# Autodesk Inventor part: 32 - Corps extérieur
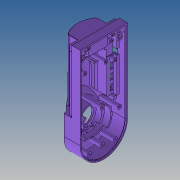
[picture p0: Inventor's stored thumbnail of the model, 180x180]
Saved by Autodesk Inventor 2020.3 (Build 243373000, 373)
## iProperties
Created: 2021-09
Part Number: 32 - Corps extérieur
Material: Aluminium 6061
Document SubType Name: Modeling
Designer: JP
Density: 2.7 g/cm^3
Appearance: Violet
Author: JP
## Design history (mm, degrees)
sketch "Esquisse1"
  geometry: L1 (-33.25, 0)-(-33.25, -115.85); L2 (-33.25, -115.85)-(33.25, -115.85); L3 (33.25, -115.85)-(33.25, 0); A1 r 33.25 centre (0, 0) between (33.25, 0) and (-33.25, 0); 1 further point
  constraints: 6 end point, 2 perpendicular, 2 point on circle, 2 tangent, 1 centre point, 1 coincident, 1 horizontal
  dimensions: "d0" = 115.85 distance of L1.start L1.end; "d1" = 33.25 radius of A1
extrude "Extrusion1" new body sketch "Esquisse1" distance "d2" = 38.6; taper "d3" = 0 deg
sketch "Esquisse2"
  geometry: L1 (0, 0)-(66.5, 0) reference; L2 (66.5, 0)-(66.5, 38.6) reference; L3 (0, 38.6)-(66.5, 38.6) reference; L4 (0, 0)-(0, 38.6) reference; L5 (33.25, -7.72)-(33.25, 46.32) reference; A1 r 33.95 centre (33.25, 4.65) between (59.533, 26.14) and (6.967, 26.14); A2 r 9 centre (66.5, 31.837) between (59.533, 26.14) and (65.6, 22.882); A3 r 1 centre (65.5, 21.887) between (66.5, 21.887) and (65.6, 22.882); A4 r 9 centre (0, 31.837) between (0.9, 22.882) and (6.967, 26.14); A5 r 1 centre (1, 21.887) between (0.9, 22.882) and (0, 21.887); 2 further points
  constraints: 10 point on circle, 5 centre point, 4 point on line, 3 tangent, 2 other
  dimensions: "d4" = 33.95 radius of A1; "d5" = 4.65 distance from line of L1 A1.centre; "d6" = 9 radius of A2; "d7" = 1 radius of A3
extrude "Extrusion2" cut sketch "Esquisse2" extent not by distance; stored distance "d8" = 0; taper "d9" = 0 deg
sketch "Esquisse3"
  geometry: L1 (0, 149.1)-(38.6, 149.1) reference; L2 (38.6, 149.1)-(38.6, 0) reference; L3 (0, 115.85)-(0, 149.1) reference; A1 r 169.8 centre (193.3, 149.1) between (23.5, 149.1) and (38.6, 79.1)
  constraints: 2 point on circle, 2 point on line, 1 centre point
  dimensions: "d10" = 339.6 diameter of A1; "d11" = 23.5 distance from line of L3 A1.start; "d12" = 70 distance from line of L1 A1.end
extrude "Extrusion3" cut sketch "Esquisse3" extent not by distance; stored distance "d13" = 0.002; taper "d14" = 0 deg
sketch "Esquisse4"
  geometry: L1 (0, 0)-(0, 21.887) reference; L2 (0, 0)-(66.5, 0) reference; L3 (66.5, 0)-(66.5, 21.887) reference; L4 (0, 11.5)-(3.5, 11.5); L5 (3.5, 11.5)-(3.5, 13.3); L6 (3.5, 13.3)-(2.075, 13.3); L7 (2.075, 13.3)-(2.075, 16.3); L8 (2.075, 16.3)-(12.75, 16.3); L9 (12.75, 27.305)-(12.75, 16.3); L10 (33.096, 23.5)-(33.404, 23.5) reference; L11 (66.5, 11.5)-(63, 11.5); L12 (63, 11.5)-(63, 13.3); L13 (63, 13.3)-(64.425, 13.3); L14 (64.425, 13.3)-(64.425, 16.3); L15 (64.425, 16.3)-(53.75, 16.3); L16 (53.75, 16.3)-(53.75, 27.305); L17 (33.25, -7.721)-(33.25, 46.324) reference; A1 r 1 centre (65.5, 21.887) between (66.5, 21.887) and (65.6, 22.882) reference; A2 r 33.95 centre (33.25, 4.65) between (59.533, 26.14) and (6.967, 26.14) reference; A3 r 1 centre (1, 21.887) between (0.9, 22.882) and (0, 21.887) reference; A4 r 32.45 centre (33.25, 4.65) between (51.573, 31.432) and (14.927, 31.432); A5 r 5 centre (17.75, 27.305) between (14.927, 31.432) and (12.75, 27.305); A6 r 5 centre (48.75, 27.305) between (53.75, 27.305) and (51.573, 31.432); A7 r 9 centre (0, 31.837) between (0.9, 22.882) and (6.967, 26.14) reference; A8 r 9 centre (66.5, 31.837) between (59.533, 26.14) and (65.6, 22.882) reference; 2 further points
  constraints: 24 end point, 10 perpendicular, 7 point on circle, 4 tangent, 3 centre point, 3 point on line, 1 equal radius, 1 horizontal, 1 parallel, 6 other
  dimensions: "d15" = 3.5 distance of L4.start L4.end; "d16" = 11.5 distance between parallel lines of L2 L11; "d17" = 1.8 distance of L4.end L5.end; "d18" = 62.35 distance between parallel lines of L14 L7; "d19" = 3 distance of L6.end L7.end; "d20" = 1.5 radial gap between concentric circles of A2 A4; "d21" = 5 radius of A5; "d23" = 41 distance between parallel lines of L16 L9
extrude "Extrusion4" cut sketch "Esquisse4" distance "d24" = 88; taper "d25" = 0 deg
sketch "Esquisse5"
  geometry: L1 (45.062, 34.874)-(48.714, 34.874) reference; L2 (49.25, 34.593)-(49.25, 32.881); L3 (33.25, -7.782)-(33.25, 46.69) reference; L4 (17.25, 34.593)-(17.25, 32.881); A1 r 32.45 centre (33.25, 4.65) between (51.573, 31.432) and (45.062, 34.874) reference; A2 r 5 centre (48.75, 27.305) between (53.75, 27.305) and (51.573, 31.432) reference; A3 r 33.95 centre (33.25, 4.65) between (59.533, 26.14) and (48.714, 34.874) reference; A4 r 33.95 centre (33.25, 4.65) between (49.25, 34.593) and (16.125, 33.964); A5 r 32.45 centre (33.25, 4.65) between (51.573, 31.432) and (16.125, 32.213); A6 r 32.45 centre (33.25, 4.65) between (21.438, 34.874) and (14.927, 31.432) reference; 11 further points
  constraints: 8 point on circle, 4 end point, 3 concentric, 2 centre point, 2 vertical, 1 coincident, 3 other
  dimensions: "d30" = 32 distance between parallel lines of L2 L4
extrude "Extrusion5" join sketch "Esquisse5" distance "d26" = 46; taper "d28" = 0 deg; dims "d27" = 28, "d29" = 0
node "Plan de construction1"
sketch "Esquisse6"
  geometry: C1 r 169.8 at (-193.3, 149.1); A1 r 169.8 centre (-193.3, 149.1) between (-34.593, 88.732) and (-32.881, 93.441) reference; 3 further points
  constraints: 2 concentric, 1 centre point, 1 other
extrude "Extrusion6" cut sketch "Esquisse6" extent not by distance; stored distance "d31" = 0.002; taper "d32" = 0 deg
sketch "Esquisse7"
  geometry: L1 (-16, 42)-(16, 42) reference; L2 (-16, 42)-(-16, 58); L3 (16, 88)-(16, 42) reference; L4 (16, 42)-(16, 58); A1 r 16 centre (0, 58) between (-16, 58) and (0, 42); A2 r 16 centre (0, 58) between (0, 42) and (16, 58); 1 further point
  constraints: 4 end point, 4 point on circle, 2 centre point, 1 concentric, 1 midpoint, 1 parallel, 1 point on line, 1 tangent, 1 vertical
  dimensions: "d33" = 16 radius of A1
extrude "Extrusion7" cut sketch "Esquisse7" stored distance "d34" = 10; taper "d35" = 0 deg; dims "d11" = 23.5
chamfer "Chanfrein1" distance "d36" = 5; stored, may be unused: second distance "d37" = 2, angle "d38" = 45 deg
node "Plan de construction2"
sketch "Esquisse8"
  geometry: L1 (0, -145.67)-(0, 63.072) reference; L2 (12, -95.15)-(-12, -95.15); L3 (-12, -95.15)-(-12, -111.15); L4 (-12, -111.15)-(12, -111.15); L5 (12, -111.15)-(12, -95.15); L6 (33.25, -115.85)-(-33.25, -115.85) reference; 1 further point
  constraints: 8 end point, 2 parallel, 1 horizontal, 1 perpendicular, 1 other
  dimensions: "d40" = 24 distance of L4.end L3.end; "d41" = 16 distance of L3.end L2.end; "d42" = 4.7 distance between parallel lines of L6 L4
extrude "Extrusion8" cut sketch "Esquisse8" extent not by distance; stored distance "d43" = 10; taper "d44" = 3.5 deg
sketch "Esquisse9"
  geometry: L1 (-112.628, 34.168)-(-93.672, 34.168) reference; L2 (-111.15, 10)-(-112.628, 34.168) reference; L3 (-111.15, 10)-(-95.15, 10) reference; L4 (-95.15, 10)-(-93.672, 34.168) reference; L5 (-111.15, 10)-(-95.15, 10) reference; L6 (-95.15, 10)-(-79.504, 37.1); L7 (-115.85, 27.305)-(-115.85, 16.3) reference; L8 (-73.85, 37.1)-(-115.85, 37.1) reference; L9 (-95.15, 10)-(-111.15, 10); L10 (-115.85, 11.5)-(-27.85, 11.5) reference; L11 (-111.15, 10)-(-112.628, 34.168) reference; L12 (-112.808, 37.1)-(-111.15, 10); A1 r 21.987 centre (-89.204, 11.342) between (-111.15, 10) and (-111.15, 10); 4 further points
  constraints: 6 end point, 3 point on line, 2 point on circle, 1 centre point, 1 collinear, 1 parallel, 1 tangent
  dimensions: "d45" = 30 deg angle of L7 L6
extrude "Extrusion9" cut sketch "Esquisse9" stored distance "d46" = 10; taper "d47" = 0 deg
mirror "Symétrie1"
sketch "Esquisse10"
  geometry: L1 (3.5, 0)-(0, 0) reference; L2 (3.5, 88)-(3.5, 0) reference; L3 (3.5, 0)-(-63, 0); L4 (-63, 0)-(-63, 2); L5 (-63, 2)-(3.5, 2); L6 (3.5, 2)-(3.5, 0); L7 (-63, 0)-(-63, 88) reference; 3 further points
  constraints: 8 end point, 2 parallel, 1 collinear, 1 horizontal, 1 perpendicular
  dimensions: "d48" = 2 distance of L3.end L4.end
extrude "Extrusion10" cut sketch "Esquisse10" extent not by distance; stored distance "d49" = 27.105; taper "d50" = 0 deg
fillet "Congé1" dims "d51" = 0.5
feature "Coque1" dims "d52" = 2
sketch "Esquisse12"
  geometry: L1 (0, 0)-(22.906, 0) reference; L2 (11.453, 40.335)-(11.453, -117.021) reference; L3 (20.453, -25)-(2.453, -25); L4 (2.453, -25)-(2.453, -2.5); L5 (2.453, -2.5)-(20.453, -2.5); L6 (20.453, -2.5)-(20.453, -25); 1 further point
  constraints: 8 end point, 2 parallel, 1 horizontal, 1 perpendicular, 1 other
  dimensions: "d58" = 18 distance of L4.end L5.end; "d59" = 2.5 distance between parallel lines of L1 L5; "d60" = 22.5 distance of L3.end L4.end
extrude "Extrusion12" cut sketch "Esquisse12" stored distance "d61" = 10; taper "d62" = 0 deg
sketch "Esquisse13"
  geometry: L1 (-1, -86)-(10.175, -86) reference; L2 (10.175, -86)-(10.175, 0) reference; L3 (-52.175, -86)-(-41, -86) reference; L4 (-41.5, -85.5)-(-41.5, -0.5) reference; L5 (-41.5, -0.5)-(-42, 0) reference; L6 (-42, 0)-(-52.175, 0) reference; L7 (-52.175, -86)-(-52.175, 0) reference; L8 (-52.25, -78)-(-44.95, -78); L9 (-41.95, -81)-(-41.95, -86); L10 (-41.95, -86)-(-52.25, -86); L11 (-52.25, -86)-(-52.25, -78); L12 (10.25, -78)-(2.95, -78); L13 (-0.05, -81)-(-0.05, -86); L14 (-0.05, -86)-(10.25, -86); L15 (10.25, -86)-(10.25, -78); L16 (12.25, -88)-(-54.25, -88) reference; L17 (-21, -117.82)-(-21, 90.922) reference; L18 (10.25, -86)-(10.25, 27.85) reference; L19 (-52.25, 27.85)-(-52.25, -86) reference; A1 r 0.5 centre (-41, -85.5) between (-41.5, -85.5) and (-41, -86) reference; A2 r 3 centre (-44.95, -81) between (-41.95, -81) and (-44.95, -78); A3 r 3 centre (2.95, -81) between (2.95, -78) and (-0.05, -81); 7 further points
  constraints: 16 end point, 4 parallel, 4 point on circle, 4 tangent, 2 centre point, 2 collinear, 2 horizontal, 2 perpendicular, 1 equal radius, 1 point on line, 1 symmetric about line, 1 other
  dimensions: "d63" = 3 radius of A2; "d64" = 10 distance between parallel lines of L16 L8; "d65" = 47.9 distance of A3.centre A2.centre
extrude "Extrusion13" join sketch "Esquisse13" stored distance "d66" = 10; taper "d67" = 0 deg
sketch "Esquisse14"
  geometry: L1 (-52.25, -86)-(-41, -86) reference; L2 (-41.5, -85.5)-(-41.5, -0.5) reference; L3 (-41.5, -0.5)-(-42, 0) reference; L4 (-42, 0)-(-52.175, 0) reference; L5 (-52.175, -78)-(-52.175, 0) reference; L6 (-52.175, -78)-(-52.25, -78) reference; L7 (-52.25, -78)-(-52.25, -86) reference; L8 (-21, -117.82)-(-21, 90.922) reference; L9 (12.25, -88)-(-54.25, -88) reference; C1 r 4.1 at (-47.4, -71.8); C2 r 4.1 at (5.4, -71.8); A1 r 0.5 centre (-41, -85.5) between (-41.5, -85.5) and (-41, -86) reference; 1 further point
  constraints: 2 centre point, 1 other
  dimensions: "d68" = 8.2 diameter of C1; "d69" = 16.2 distance from line of L9 C1.centre; "d70" = 52.8 distance of C2.centre C1.centre
extrude "Extrusion14" join sketch "Esquisse14" distance "d71" = 2; taper "d73" = 0 deg; dims "d72" = 12.2, "d74" = 0
sketch "Esquisse15"
  geometry: L1 (-26.4, -46.02)-(-26.4, 162.722) reference; L2 (6.85, -16.2)-(-59.65, -16.2) reference; C1 r 2.5 at (-9.65, -7.9); C2 r 2.5 at (-43.15, -7.9); 1 further point
  constraints: 2 centre point, 1 other
  dimensions: "d75" = 5 diameter of C1; "d76" = 8.3 distance from line of L2 C2.centre; "d77" = 33.5 distance of C1.centre C2.centre
extrude "Extrusion15" join sketch "Esquisse15" stored distance "d78" = 10; taper "d79" = 0 deg
node "Plan de construction3"
sketch "Esquisse16"
  geometry: L1 (27.75, -119.82)-(27.75, 88.922) reference; L2 (61, -90)-(-5.5, -90) reference; C1 r 2.5 at (13.25, -46.3); C2 r 2.5 at (5.75, -68.1); C3 r 2.5 at (42.25, -46.3); C4 r 2.5 at (49.75, -68.1); 1 further point
  constraints: 4 centre point, 1 equal radius, 2 other
  dimensions: "d81" = 5 diameter of C1; "d82" = 43.7 distance from line of C1.centre L2; "d83" = 21.9 distance from line of L2 C2.centre; "d84" = 29 distance of C3.centre C1.centre; "d85" = 44 distance of C4.centre C2.centre
extrude "Extrusion16" join sketch "Esquisse16" stored distance "d86" = 10; taper "d87" = 0 deg
node "Plan de construction4"
sketch "Esquisse17"
  geometry: L1 (27.75, -119.82)-(27.75, 88.922) reference; L2 (61, -90)-(-5.5, -90) reference; C1 r 2.5 at (2.75, 1.2); C2 r 2.5 at (52.75, 1.2); C3 r 2.5 at (2.75, -44.7); C4 r 2.5 at (52.75, -44.7); 1 further point
  constraints: 4 centre point, 1 equal radius, 1 vertical alignment, 2 other
  dimensions: "d89" = 5 diameter of C1; "d90" = 45.3 distance from line of L2 C3.centre; "d91" = 50 distance of C4.centre C3.centre; "d92" = 45.9 distance of C1.centre C3.centre
extrude "Extrusion17" join sketch "Esquisse17" stored distance "d93" = 10; taper "d94" = 0 deg
sketch "Esquisse18"
  geometry: L1 (0, -145.67)-(0, 63.072) reference; L2 (33.25, -115.85)-(-33.25, -115.85) reference; C1 r 3 at (-18.2, 18.949); C2 r 3 at (18.2, 18.949); C3 r 3 at (23.95, -17.5); C4 r 3 at (-23.95, -17.5); C5 r 3 at (0, -28.95); C6 r 3 at (0, 16.65); A1 r 3 centre (-23.95, -108.85) between (-20.95, -108.85) and (-23.95, -105.85) reference; A2 r 31.25 centre (0, 0) between (31.25, 0) and (-31.25, 0) reference; A3 r 3 centre (23.95, -108.85) between (23.95, -105.85) and (20.95, -108.85) reference
  constraints: 6 centre point, 3 equal radius, 2 point on line, 2 other
  dimensions: "d95" = 6 diameter of C1; "d96" = 36.4 distance of C2.centre C1.centre; "d97" = 91.35 distance of A1.centre C4.centre; "d98" = 47.9 distance of C3.centre C4.centre; "d99" = 36.9 distance of C4.centre C1.centre; "d100" = 45.6 distance of C6.centre C5.centre; "d101" = 11.45 vertical distance of C3.centre C5.centre; "d229" = 7 distance from line of L2 A1.centre (derived); "d230" = 17.5 vertical distance of C3.centre A2.centre (derived); "d231" = 108.85 vertical distance of A3.centre A2.centre (derived)
extrude "Extrusion18" join sketch "Esquisse18" stored distance "d102" = 10; taper "d103" = 0 deg
sketch "Esquisse19"
  geometry: L1 (-23.95, -39.82)-(-23.95, 168.922) reference; L2 (-0.9, 75.2)-(3.1, 75.2); L3 (3.1, 75.2)-(3.1, 67.2); L4 (3.1, 67.2)-(-0.9, 67.2); L5 (-0.9, 67.2)-(-0.9, 75.2); L6 (-0.9, 62.2)-(3.1, 62.2); L7 (3.1, 62.2)-(3.1, 54.2); L8 (3.1, 54.2)-(-0.9, 54.2); L9 (-0.9, 54.2)-(-0.9, 62.2); L10 (-0.9, 49.2)-(3.1, 49.2); L11 (3.1, 49.2)-(3.1, 41.2); L12 (3.1, 41.2)-(-0.9, 41.2); L13 (-0.9, 41.2)-(-0.9, 49.2); L14 (-51, 75.2)-(-47, 75.2); L15 (-47, 75.2)-(-47, 67.2); L16 (-47, 67.2)-(-51, 67.2); L17 (-51, 67.2)-(-51, 75.2); L18 (-51, 62.2)-(-47, 62.2); L19 (-47, 62.2)-(-47, 54.2); L20 (-47, 54.2)-(-51, 54.2); L21 (-51, 54.2)-(-51, 62.2); L22 (-51, 49.2)-(-47, 49.2); L23 (-47, 49.2)-(-47, 41.2); L24 (-47, 41.2)-(-51, 41.2); L25 (-51, 41.2)-(-51, 49.2); L26 (9.3, 105.85)-(9.3, -10) reference; C1 r 2.5 at (1.05, 35.3) reference; C2 r 2.5 at (1.05, 35.3) reference; 1 further point
  constraints: 48 end point, 12 parallel, 6 horizontal, 6 perpendicular, 5 collinear, 5 point on line, 4 equal length, 4 other
  dimensions: "d104" = 4 distance of L3.end L4.end; "d105" = 8 distance of L2.end L3.end; "d106" = 5 distance between parallel lines of L6 L4; "d107" = 5 distance between parallel lines of L10 L8 (= d106); "d108" = 5.9 distance from line of C1.centre L12; "d109" = 6.2 distance between parallel lines of L26 L7
extrude "Extrusion19" cut sketch "Esquisse19" extent not by distance; stored distance "d110" = 14.3; taper "d111" = 0 deg
sketch "Esquisse20"
  geometry: L1 (10.175, -78)-(10.175, 0) reference; L2 (5.85, -46.1)-(10.25, -46.1); L3 (10.25, -46.1)-(10.25, -54.4); L4 (10.25, -54.4)-(5.85, -54.4); L5 (5.85, -54.4)-(5.85, -46.1); L6 (12.25, -88)-(-54.25, -88) reference; L7 (12.25, 0)-(12.25, -88) reference; L8 (10.25, -78)-(10.25, 27.85) reference; 3 further points
  constraints: 8 end point, 2 parallel, 1 collinear, 1 horizontal, 1 perpendicular
  dimensions: "d112" = 4.4 distance of L3.end L4.end; "d113" = 8.3 distance of L2.end L3.end; "d114" = 33.6 distance between parallel lines of L6 L4
extrude "Extrusion20" cut sketch "Esquisse20" extent not by distance; stored distance "d116" = 22.305; taper "d117" = 0 deg
sketch "Esquisse21"
  geometry: L1 (0, 10.071)-(0, 23.6) reference; L2 (9.25, 0.085)-(9.25, 78.328) reference; L3 (0, 31.9)-(0.9, 31.9) reference; L4 (0, 16.6)-(9.25, 16.6); L5 (9.25, 16.6)-(9.25, 31.9); L6 (9.25, 31.9)-(0, 31.9); L7 (0, 31.9)-(0, 16.6); L8 (0, 10.071)-(0, 23.6) reference; 7 further points
  constraints: 8 end point, 3 collinear, 2 parallel, 1 horizontal, 1 perpendicular
  dimensions: "d118" = 15.3 distance of L5.end L4.end
extrude "Extrusion21" cut sketch "Esquisse21" distance "d119" = 1; taper "d120" = 0 deg
sketch "Esquisse22"
  geometry: L1 (9.25, 16.6)-(0, 16.6) reference; L2 (9.25, 31.9)-(9.25, 16.6) reference; L3 (9.25, 22.1)-(11.25, 22.1); L4 (11.25, 22.1)-(11.25, 18.1); L5 (11.25, 18.1)-(9.25, 18.1); L6 (9.25, 18.1)-(9.25, 22.1); 2 further points
  constraints: 8 end point, 2 parallel, 1 horizontal, 1 perpendicular, 1 point on line
  dimensions: "d121" = 2 distance of L4.end L5.end; "d122" = 4 distance of L3.end L4.end; "d123" = 1.5 distance between parallel lines of L1 L5
extrude "Extrusion22" join sketch "Esquisse22" stored distance "d124" = 10; taper "d125" = 0 deg
sketch "Esquisse23"
  geometry: L1 (-31.25, -105.85)-(-31.25, 0) reference; L2 (31.25, 0)-(31.25, -105.85) reference; L3 (20.95, -113.85)-(-20.95, -113.85) reference; L4 (-31.85, -16.807)-(-31.85, -113.85); L5 (-31.85, -113.85)-(31.85, -113.85); L6 (31.85, -113.85)-(31.85, -105.85); L7 (0, -163.681)-(0, 66.074) reference; L8 (-31.85, -105.85)-(-31.85, 0); L9 (31.85, 0)-(31.85, -105.85); A1 r 31.25 centre (0, 0) between (31.25, 0) and (-31.25, 0) reference; A2 r 31.85 centre (0, 0) between (31.85, 0) and (-31.85, 0); 3 further points
  constraints: 10 end point, 2 point on circle, 1 centre point, 1 collinear, 1 horizontal, 1 parallel, 1 vertical, 3 other
  dimensions: "d127" = 0.6 distance between parallel lines of L1 L8
extrude "Extrusion23" cut sketch "Esquisse23" distance "d128" = 1.8; taper "d129" = 0 deg
sketch "Esquisse24"
  geometry: L1 (15.35, 23.045)-(15.35, 9.8); L2 (15.35, 9.8)-(13.35, 9.8); L3 (13.35, 9.8)-(13.35, 18.8); L4 (13.35, 18.8)-(-6.15, 18.8); L5 (-6.15, 18.8)-(-6.15, 28.7); L6 (-6.15, 28.7)-(6.034, 28.7); L7 (31.85, 0)-(0, 0) reference; L8 (-6.15, 32.047)-(-6.15, -7.064); L9 (-115.85, 0)-(-115.85, 11.5) reference; L10 (9.85, 30.1)-(12.537, 30.1); L11 (9.85, 30.1)-(9.85, 38.722); L12 (48.38, 30.5)-(-23.26, 30.5); L13 (10.542, 29.822)-(16.25, 24.353); L14 (33.25, 0)-(33.25, 23.5) reference; A1 r 1.4 centre (16.75, 23.045) between (16.25, 24.353) and (15.35, 23.045); A2 r 4.9 centre (6.034, 33.6) between (6.034, 28.7) and (9.203, 29.863); A3 r 1 centre (9.85, 29.1) between (10.542, 29.822) and (9.203, 29.863); 2 further points
  constraints: 22 end point, 7 point on circle, 5 perpendicular, 5 tangent, 3 centre point, 3 vertical, 2 horizontal, 1 collinear, 2 other
  dimensions: "d130" = 2 distance of L1.end L2.end; "d131" = 9 distance of L2.end L3.end; "d132" = 9.8 distance between parallel lines of L7 L2; "d133" = 109.7 distance between parallel lines of L8 L9; "d134" = 39 diameter of L3 L8; "d135" = 1 radius of A3; "d136" = 4.9 radius of A2; "d138" = 30.5 distance between parallel lines of L7 L12; "d140" = 32 diameter of L11 L8; "d141" = 1.8 distance between parallel lines of L12 L6; "d142" = 17 distance from line of L13.end L14; "d143" = 1.4 radius of A1; "d145" = 1.4 distance between parallel lines of L6 L10
revolve "Révolution1" sketch "Esquisse24" stored, may be unused: angle "d144" = 90 deg
sketch "Esquisse25"
  geometry: A1 r 21.5 centre (0, 22.8) between (2.621, 1.46) and (2.621, 44.14) reference; A2 r 21.5 centre (0, 22.8) between (-2.621, 44.14) and (-2.621, 1.46) reference; A3 r 22.4 centre (0, 22.8) between (2.941, 0.594) and (20.837, 31.02) reference; A4 r 22.4 centre (0, 22.8) between (-20.837, 31.02) and (-2.941, 0.594) reference; 7 further points
  constraints: 3 other
extrude "Extrusion24" cut sketch "Esquisse25" stored distance "d146" = 10; taper "d147" = 0 deg; dims "d11" = 23.5
sketch "Esquisse26"
  geometry: A1 r 3 centre (0, 0) between (2.621, 1.46) and (-2.621, 1.46) reference; A2 r 21.5 centre (0, 22.8) between (2.621, 1.46) and (2.621, 44.14) reference; A3 r 3 centre (0, 45.6) between (-2.621, 44.14) and (2.621, 44.14) reference; A4 r 21.5 centre (0, 22.8) between (-2.621, 44.14) and (-2.621, 1.46) reference; 1 further point
extrude "Extrusion25" join sketch "Esquisse26" stored distance "d148" = 10; taper "d149" = 0 deg
node "Axe de construction1"
sketch "Esquisse27"
  geometry: L1 (10.934, 33.6)-(-6.15, 33.6); L2 (-6.15, 33.6)-(-6.15, 28.7); L3 (-6.15, 28.7)-(6.034, 28.7); L4 (-8.45, 28.7)-(6.034, 28.7) reference; L5 (-6.15, 46.326)-(-6.15, -7.721) reference; A1 r 4.9 centre (6.034, 33.6) between (6.034, 28.7) and (10.934, 33.6); A2 r 4.9 centre (6.034, 33.6) between (6.034, 28.7) and (9.203, 29.863) reference; 5 further points; 2 other entities
  constraints: 6 end point, 2 coincident, 2 collinear, 2 perpendicular, 2 point on circle, 1 centre point, 1 concentric, 1 horizontal, 1 point on line, 1 tangent
revolve "Révolution2" sketch "Esquisse27" stored, may be unused: angle "d150" = 90 deg
fillet "Congé2" dims "d151" = 3
sketch "Esquisse28"
  geometry: C1 r 12.184 at (0, 0) reference; C2 r 12 at (0, 0); 1 further point
  constraints: 1 centre point, 1 coincident
  dimensions: "d152" = 24 diameter of C2
extrude "Extrusion26" cut sketch "Esquisse28" distance "d153" = 2; taper "d154" = 0 deg
sketch "Esquisse29"
  geometry: C1 r 12 at (0, 0) reference; C2 r 16 at (0, 0); 1 further point
  constraints: 1 centre point, 1 coincident
  dimensions: "d155" = 32 diameter of C2
extrude "Extrusion27" cut sketch "Esquisse29" distance "d156" = 7.9; taper "d157" = 0 deg
sketch "Esquisse30"
  geometry: C1 r 16 at (0, 0) reference; C2 r 19.5 at (0, 0); 1 further point
  constraints: 1 centre point, 1 coincident
  dimensions: "d158" = 39 diameter of C2
extrude "Extrusion28" cut sketch "Esquisse30" extent not by distance; stored distance "d159" = 19.805; taper "d160" = 0 deg
sketch "Esquisse31"
  geometry: L1 (0, -116.72)-(0, 92.022) reference; L2 (-15.932, 8.363)-(15.932, 37.237); L3 (15.932, 8.363)-(-15.932, 37.237); L4 (0, 22.8)-(-7.634, 22.8); L5 (15.932, 8.363)-(14.45, 9.706); L6 (-15.932, 8.363)-(-14.45, 9.706); L7 (-14.45, 35.894)-(-15.932, 37.237); L8 (14.45, 35.894)-(15.932, 37.237); C1 r 19.5 at (0, 22.8) reference; A1 r 3 centre (0, 0) between (2.621, 1.46) and (-2.621, 1.46) reference; A2 r 21.5 centre (0, 22.8) between (2.621, 1.46) and (2.621, 44.14) reference; A3 r 3 centre (0, 45.6) between (-2.621, 44.14) and (2.621, 44.14) reference; A4 r 21.5 centre (0, 22.8) between (-2.621, 44.14) and (-2.621, 1.46) reference; A5 r 19.5 centre (0, 22.8) between (14.45, 9.706) and (-14.45, 9.706) reference; 5 further points
  constraints: 14 end point, 9 point on circle, 5 point on line, 3 collinear, 1 horizontal, 2 other
  dimensions: "d232" = 28.9 distance of L6.end L5.end
extrude "Extrusion29" cut sketch "Esquisse31" distance "d162" = 6.4; taper "d163" = 0 deg
sketch "Esquisse32"
  geometry: L1 (0, -139.52)-(0, 69.222) reference; L2 (-1, 19.474)-(-1, 15.969); L3 (1, 19.474)-(1, 15.969); A1 r 16 centre (0, 0) between (-1, 15.969) and (1, 15.969) reference; A2 r 19.5 centre (0, 0) between (-1, 19.474) and (1, 19.474) reference; A3 r 19.5 centre (0, 0) between (1, 19.474) and (-1, 19.474); A4 r 16 centre (0, 0) between (1, 15.969) and (-1, 15.969); 1 further point
  constraints: 9 point on circle, 4 end point, 2 centre point, 2 concentric, 1 vertical, 1 other
  dimensions: "d164" = 2 distance between parallel lines of L3 L2
extrude "Extrusion30" cut sketch "Esquisse32" stored distance "d165" = 10; taper "d166" = 0 deg
pattern_circular "Réseau circulaire1" dims angle "d168" = 360 deg
sketch "Esquisse33"
  geometry: L1 (-15.932, -14.437)-(-14.45, -13.094) reference; L2 (14.45, -13.094)-(15.932, -14.437) reference; L3 (15.932, 14.437)-(14.45, 13.094) reference; L4 (-14.45, 13.094)-(-15.932, 14.437) reference; L5 (14.45, -13.094)-(11.856, -10.744); L6 (-14.45, -13.094)-(-11.856, -10.744); L7 (11.856, 10.744)-(14.45, 13.094); L8 (-11.856, 10.744)-(-14.45, 13.094); L9 (0, 0)-(-9.574, 0); A1 r 16 centre (0, 0) between (-8.85, 13.329) and (-8.85, -13.329) reference; A2 r 19.5 centre (0, 0) between (-10.603, 16.365) and (-10.603, -16.365) reference; A3 r 16 centre (0, 0) between (8.85, -13.329) and (8.85, 13.329) reference; A4 r 16 centre (0, 0) between (11.856, 10.744) and (-11.856, 10.744); A5 r 16 centre (0, 0) between (-11.856, -10.744) and (11.856, -10.744); A6 r 16 centre (0, 0) between (8.85, -13.329) and (8.85, 13.329) reference; A7 r 19.5 centre (0, 0) between (-14.45, -13.094) and (14.45, -13.094) reference; A8 r 21.5 centre (0, 0) between (-15.932, -14.437) and (-2.621, -21.34) reference; A9 r 3 centre (0, -22.8) between (2.621, -21.34) and (-2.621, -21.34) reference; A10 r 21.5 centre (0, 0) between (2.621, -21.34) and (15.932, -14.437) reference; A11 r 19.5 centre (0, 0) between (14.45, 13.094) and (-14.45, 13.094) reference; A12 r 21.5 centre (0, 0) between (15.932, 14.437) and (2.621, 21.34) reference; A13 r 3 centre (0, 22.8) between (-2.621, 21.34) and (2.621, 21.34) reference; A14 r 21.5 centre (0, 0) between (-2.621, 21.34) and (-15.932, 14.437) reference; 9 further points
  constraints: 10 end point, 8 point on circle, 3 collinear, 3 concentric, 2 centre point, 1 horizontal, 1 point on line, 1 other
extrude "Extrusion31" cut sketch "Esquisse33" distance "d170" = 4.8; taper "d171" = 0 deg
node "Plan de construction5"
sketch "Esquisse34"
  geometry: L1 (6.5, -49.3)-(6.5, -2.872) reference; L2 (43.5, -81.115)-(43.5, -2.872) reference; L3 (6.5, -43.2)-(16.35, -43.2); L4 (16.35, -43.2)-(16.35, -45.2); L5 (16.35, -45.2)-(6.5, -45.2); L6 (6.5, -45.2)-(6.5, -43.2); L7 (43.5, -43.2)-(33.65, -43.2); L8 (33.65, -43.2)-(33.65, -45.2); L9 (33.65, -45.2)-(43.5, -45.2); L10 (43.5, -45.2)-(43.5, -43.2); L11 (25, -121.02)-(25, 87.722) reference; L12 (58.25, -91.2)-(-8.25, -91.2) reference; 3 further points
  constraints: 16 end point, 4 parallel, 3 point on line, 2 horizontal, 2 perpendicular, 1 collinear, 3 other
  dimensions: "d173" = 2 distance of L3.end L4.end; "d174" = 17.3 distance between parallel lines of L8 L4; "d175" = 48 distance between parallel lines of L12 L3
extrude "Extrusion32" join sketch "Esquisse34" stored distance "d176" = 10; taper "d177" = 0 deg; dims "d11" = 23.5
sketch "Esquisse35"
  geometry: C1 r 2.5 at (0, 0) reference; C2 r 2.5 at (44, 0) reference; 3 further points
  constraints: 2 coincident
hole "Perçage1" sketch "Esquisse35" at (0, 0), (44, 0) diameter "d178" = 2.459; stored, may be unused: countersink angle "d182" = 90 deg, drill point angle "d184" = 118 deg; dims "d179" = 6, "d180" = 9.4, "d181" = 2, "d183" = 8.8
sketch "Esquisse36"
  geometry: C1 r 3 at (-18.2, 18.949) reference; C2 r 3 at (18.2, 18.949) reference; C3 r 3 at (23.95, -17.5) reference; C4 r 3 at (0, -28.95) reference; C5 r 3 at (-23.95, -17.5) reference; C6 r 3 at (0, 16.65) reference; A1 r 3 centre (-23.95, -108.85) between (-20.95, -108.85) and (-23.95, -105.85) reference; A2 r 3 centre (23.95, -108.85) between (23.95, -105.85) and (20.95, -108.85) reference; 9 further points
  constraints: 8 coincident
hole "Perçage2" sketch "Esquisse36" at (-18.2, 18.949), (0, 16.65), (18.2, 18.949), (23.95, -17.5), (0, -28.95), (-23.95, -17.5), (-23.95, -108.85), (23.95, -108.85) diameter "d185" = 2.459; stored, may be unused: countersink angle "d189" = 90 deg, drill point angle "d191" = 118 deg; dims "d186" = 6, "d187" = 9.4, "d188" = 2, "d190" = 10
sketch "Esquisse40"
  geometry: L1 (-7.984, 85.386)-(-7.984, 87.154) reference; L2 (-3.422, 81.7)-(-6.057, 81.7) reference; L3 (-3.422, 81.7)-(2.75, 75.528) reference; L4 (2.75, 75.528)-(2.75, 49.7) reference; L5 (30.75, 75.528)-(30.75, 49.7) reference; L6 (30.75, 75.528)-(36.922, 81.7) reference; L7 (39.557, 81.7)-(36.922, 81.7) reference; L8 (41.484, 85.386)-(41.484, 87.154) reference; L9 (41.484, 92.946)-(41.484, 106.918) reference; L10 (-7.984, 92.946)-(-7.984, 106.918) reference; C1 r 2.5 at (0, 0) reference; C2 r 2.5 at (33.5, 0) reference; 6 further points
  constraints: 2 coincident, 2 vertical alignment, 1 horizontal alignment, 6 other
hole "Perçage5" sketch "Esquisse40" at (0, 0), (33.5, 0) diameter "d208" = 2.459; stored, may be unused: countersink angle "d212" = 90 deg, drill point angle "d214" = 118 deg; dims "d209" = 6, "d210" = 9.4, "d211" = 2, "d213" = 10
sketch "Esquisse41"
  geometry: C1 r 2.5 at (0, 0) reference; C2 r 2.5 at (29, 0) reference; 3 further points
  constraints: 2 coincident
hole "Perçage6" sketch "Esquisse41" at (0, 0), (29, 0) diameter "d215" = 2.459; stored, may be unused: countersink angle "d219" = 90 deg, drill point angle "d221" = 118 deg; dims "d216" = 6, "d217" = 9.4, "d218" = 2, "d220" = 10
sketch "Esquisse42"
  geometry: C1 r 2.5 at (50, 0) reference; C2 r 2.5 at (0, 0) reference; C3 r 2.5 at (50, 0) reference; 3 further points
  constraints: 2 coincident
hole "Perçage7" sketch "Esquisse42" at (0, 0), (50, 0) diameter "d222" = 2.459; stored, may be unused: countersink angle "d226" = 90 deg, drill point angle "d228" = 118 deg; dims "d223" = 5, "d224" = 9.4, "d225" = 2, "d227" = 6.5
sketch "Esquisse37"
  geometry: L1 (66.5, 11.5)-(0, 11.5) reference; L2 (63, 13.3)-(63, 11.5) reference; L3 (63, 11.5)-(64.5, 11.5) reference; L4 (64.425, 13.3)-(63, 13.3) reference; L5 (64.5, 16.3)-(64.5, 11.5) reference; L6 (66.5, 21.887)-(66.5, 11.5) reference; L7 (64.5, 16.3)-(66.5, 16.3); L8 (66.5, 0)-(66.5, 21.887) reference; L9 (3.5, 11.5)-(3.5, 13.3) reference; L10 (3.5, 13.3)-(2.075, 13.3) reference; L11 (0, 11.5)-(0, 21.887) reference; L12 (2, 16.3)-(2, 11.5) reference; L13 (2, 16.3)-(0, 16.3); L14 (3.5, 13.3)-(2.75, 13.3) reference; L15 (3.5, 13.3)-(2, 13.3); L16 (63, 11.5)-(63, 13.3) reference; L17 (63, 13.3)-(64.5, 13.3); 4 further points
  constraints: 8 end point, 5 point on line, 3 perpendicular
extrude "Extrusion33" cut sketch "Esquisse37" stored distance "d192" = 10; taper "d193" = 0 deg
sketch "Esquisse38"
  geometry: C1 r 4.1 at (0, 0) reference; C2 r 4.1 at (52.8, 0) reference; 3 further points
  constraints: 2 coincident
hole "Perçage3" sketch "Esquisse38" at (0, 0), (52.8, 0) diameter "d194" = 4.917; stored, may be unused: countersink angle "d198" = 90 deg, drill point angle "d200" = 118 deg; dims "d195" = 12, "d196" = 9.4, "d197" = 2, "d199" = 17.1
node "Solide1"
node "Boucle projetée1"
node "Boucle projetée2"
node "Boucle projetée3"
node "Boucle projetée4"
node "Boucle projetée5"
node "Boucle projetée6"
node "Boucle projetée11"
node "Boucle projetée12"
node "Boucle projetée13"
node "Boucle projetée14"
node "Boucle projetée15"
node "Boucle projetée16"
node "Boucle projetée18"
node "Boucle projetée19"
node "Boucle projetée20"
node "Boucle projetée21"
node "Boucle projetée22"
node "Boucle projetée23"
other parameters: "d80" = 2.8, "d88" = 5.4, "d172" = -7.4
